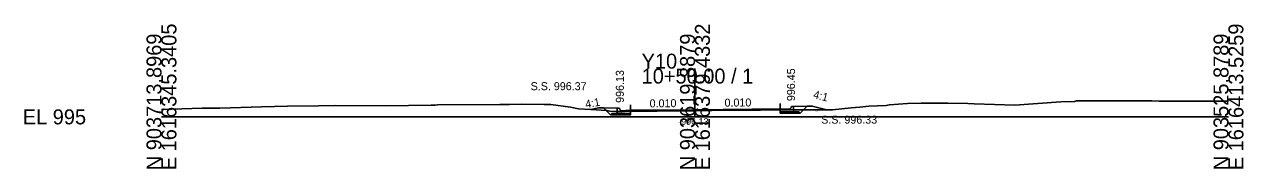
# Model space of a CAD drawing. Extents: x -26 to 203, y -10 to 3046.
# Drawn here: x -25.7 to 202.8, y 490.3 to 517.3 of the extents above; entities that cross this region are included whole.
import ezdxf

# ---------------------------------------------------------------- set-up
doc = ezdxf.new("R2010")
doc.units = 0
for name, color, linetype in [('Exist Cross Section Cell', 7, 'Continuous'), ('Exist XS Center Line Elevation Label', 7, 'Continuous'), ('Exist XS Ground Line', 7, 'Continuous'), ('Prop XS Dump Level', 7, 'Continuous'), ('Prop XS Earthwork Shape', 7, 'Continuous'), ('Prop XS EOT Tick Mark', 7, 'Continuous'), ('Prop XS Finish Grade CurbGutter', 7, 'Continuous'), ('Prop XS Finish Grade Earthwork', 7, 'Continuous'), ('Prop XS Finish Grade Pavement', 7, 'Continuous'), ('Prop XS Hydro Elevations', 7, 'Continuous'), ('Prop XS Pvmt Edge Slope', 7, 'Continuous'), ('Prop XS SE Text', 7, 'Continuous'), ('Prop XS Side Slope Text', 7, 'Continuous'), ('Prop XS SS Elevation Text', 7, 'Continuous'), ('Prop XS Subgrade CurbGutter', 7, 'Continuous'), ('Prop XS Subgrade Earthwork', 7, 'Continuous')]:
    doc.layers.add(name, color=color, linetype=linetype)

msp = doc.modelspace()

# ---------------------------------------------------------------- linework, layer by layer
at = {"layer": 'Exist Cross Section Cell'}
for p, q in [((100, 500), (100, 509.04)), ((0, 500), (100, 500)), ((100, 500), (200, 500))]:
    msp.add_line(p, q, dxfattribs=at)
at = {"layer": 'Exist XS Ground Line'}
for p, q in [((159.97, 502.21), (168.55, 502.81)), ((168.55, 502.81), (171.14, 502.88)), ((171.14, 502.88), (171.57, 503.01)), ((171.57, 503.01), (172.61, 503)), ((172.61, 503), (175.59, 502.98)), ((175.59, 502.98), (184.21, 503)), ((184.21, 503), (185.63, 502.99)), ((185.63, 502.99), (186.98, 502.96)), ((186.98, 502.96), (195.33, 502.93)), ((195.33, 502.93), (197.66, 502.94)), ((197.66, 502.94), (200, 502.95)), ((0, 501.41), (7.66, 501.62)), ((7.66, 501.62), (10.95, 501.66)), ((10.95, 501.66), (18.76, 501.85)), ((18.76, 501.85), (23.63, 501.98)), ((23.63, 501.98), (29.42, 502.05)), ((29.42, 502.05), (32.71, 502.1)), ((32.71, 502.1), (42.06, 502.09)), ((42.06, 502.09), (50.58, 502.19)), ((50.58, 502.19), (51.28, 502.21)), ((51.28, 502.21), (51.72, 502.23)), ((51.72, 502.23), (63.41, 502.29)), ((63.41, 502.29), (65.25, 502.34)), ((65.25, 502.34), (67.55, 502.39)), ((67.55, 502.39), (71.76, 502.34)), ((71.76, 502.34), (73, 502.31)), ((73, 502.31), (76.67, 501.8)), ((76.67, 501.8), (78.2, 501.5)), ((78.2, 501.5), (80.49, 501.37)), ((80.49, 501.37), (83.42, 501.2)), ((83.42, 501.2), (84.07, 501.05)), ((84.07, 501.05), (85.23, 501.03)), ((85.23, 501.03), (86.1, 501.02)), ((86.1, 501.02), (87.82, 501.05)), ((87.82, 501.05), (92.9, 501.1)), ((92.9, 501.1), (94.69, 501.14)), ((94.69, 501.14), (100.24, 501.13)), ((100.24, 501.13), (106.07, 501.24)), ((106.07, 501.24), (109.24, 501.26)), ((109.24, 501.26), (112.27, 501.27)), ((112.27, 501.27), (116.88, 501.29)), ((116.88, 501.29), (122.28, 501.32)), ((122.28, 501.32), (122.64, 501.32)), ((122.64, 501.32), (125.04, 501.33)), ((125.04, 501.33), (125.75, 501.33)), ((125.75, 501.33), (129.3, 501.69)), ((129.3, 501.69), (130.91, 501.84)), ((130.91, 501.84), (132.59, 501.98)), ((132.59, 501.98), (135.86, 502.14)), ((135.86, 502.14), (136.46, 502.27)), ((136.46, 502.27), (139.85, 502.53)), ((139.85, 502.53), (142.37, 502.57)), ((142.37, 502.57), (147.48, 502.59)), ((147.48, 502.59), (151.15, 502.5)), ((151.15, 502.5), (152.31, 502.46)), ((152.31, 502.46), (159.97, 502.21))]:
    msp.add_line(p, q, dxfattribs=at)
at = {"layer": 'Prop XS Dump Level'}
for p, q in [((100, 501.35), (87.92, 501.23)), ((116, 501.51), (100, 501.35))]:
    msp.add_line(p, q, dxfattribs=at)
at = {"layer": 'Prop XS Earthwork Shape'}
for points in [[(80.56, 501.36), (83.33, 501.2), (82.85, 501.68), (81.92, 501.7)], [(83.33, 501.2), (83.42, 501.2), (84.07, 501.05), (85.23, 501.03), (85.42, 501.03), (85.42, 500.63), (84.42, 500.62), (84.17, 500.36)], [(87.92, 500.65), (85.42, 500.63), (84.42, 500.62), (84.17, 500.36), (87.92, 500.4)], [(85.42, 501.03), (86.1, 501.02), (87.82, 501.05), (87.92, 501.05), (87.92, 500.65), (85.42, 500.63)], [(116, 501.29), (116.88, 501.29), (118.5, 501.3), (118.5, 500.96), (116, 500.93)], [(119.5, 500.97), (119.75, 500.72), (116, 500.68), (116, 500.93), (118.5, 500.96)], [(118.5, 501.3), (120.34, 501.31), (119.75, 500.72), (119.5, 500.97), (118.5, 500.96)], [(120.34, 501.31), (121.02, 501.99), (122, 502.01), (124.69, 501.33), (122.64, 501.32), (122.28, 501.32)]]:
    msp.add_lwpolyline(points, close=True, dxfattribs=at)
at = {"layer": 'Prop XS EOT Tick Mark'}
for p, q in [((87.92, 501.23), (87.92, 502.23)), ((116, 501.51), (116, 502.51))]:
    msp.add_line(p, q, dxfattribs=at)
at = {"layer": 'Prop XS Finish Grade CurbGutter'}
for p, q in [((85.42, 501.63), (85.67, 501.63)), ((85.67, 501.63), (85.79, 501.6)), ((85.89, 501.51), (85.79, 501.6)), ((85.95, 501.26), (85.89, 501.51)), ((86.04, 501.17), (85.95, 501.26)), ((86.17, 501.14), (86.04, 501.17)), ((87.92, 501.23), (86.17, 501.14)), ((116, 501.51), (117.75, 501.46)), ((117.75, 501.46), (117.87, 501.48)), ((117.87, 501.48), (117.97, 501.57)), ((117.97, 501.57), (118.03, 501.82)), ((118.03, 501.82), (118.12, 501.92)), ((118.25, 501.95), (118.12, 501.92)), ((118.5, 501.95), (118.25, 501.95))]:
    msp.add_line(p, q, dxfattribs=at)
at = {"layer": 'Prop XS Finish Grade Earthwork'}
for p, q in [((80.56, 501.36), (81.92, 501.7)), ((85.42, 501.63), (81.92, 501.7)), ((118.5, 501.95), (122, 502.01)), ((122, 502.01), (124.69, 501.33))]:
    msp.add_line(p, q, dxfattribs=at)
at = {"layer": 'Prop XS Finish Grade Pavement'}
for p, q in [((87.92, 501.23), (100, 501.35)), ((100, 501.35), (116, 501.51))]:
    msp.add_line(p, q, dxfattribs=at)
at = {"layer": 'Prop XS Pvmt Edge Slope'}
for p, q in [((84.42, 500.62), (84.17, 500.36)), ((85.42, 500.63), (84.42, 500.62)), ((118.5, 500.96), (119.5, 500.97)), ((119.5, 500.97), (119.75, 500.72))]:
    msp.add_line(p, q, dxfattribs=at)
at = {"layer": 'Prop XS Subgrade CurbGutter'}
for p, q in [((85.42, 500.63), (85.42, 501.63)), ((87.92, 500.65), (85.42, 500.63)), ((87.92, 501.23), (87.92, 500.65)), ((116, 501.51), (116, 500.93)), ((116, 500.93), (118.5, 500.96)), ((118.5, 500.96), (118.5, 501.95))]:
    msp.add_line(p, q, dxfattribs=at)
at = {"layer": 'Prop XS Subgrade Earthwork'}
for p, q in [((84.17, 500.36), (82.85, 501.68)), ((87.92, 500.65), (87.92, 501.05)), ((87.92, 500.65), (87.92, 500.4)), ((116, 500.93), (116, 501.29)), ((116, 500.93), (116, 500.68)), ((116, 500.68), (119.75, 500.72)), ((119.75, 500.72), (121.04, 502.01)), ((87.92, 500.4), (84.17, 500.36))]:
    msp.add_line(p, q, dxfattribs=at)

# ---------------------------------------------------------------- texts
at = {"layer": 'Exist Cross Section Cell'}
for s, p in [('E 1616345.3405', (2.8, 490)), ('E 1616379.4332', (102.8, 490)), ('E 1616413.5259', (202.8, 490)), ('N 903713.8969', (0, 490)), ('N 903619.8879', (100, 490)), ('N 903525.8789', (200, 490))]:
    msp.add_text(s, height=2.8, rotation=90, dxfattribs=at).set_placement(p)
for s, p in [('Y10', (90, 509.04)), ('10+50.00 / 1', (90, 506.24)), ('EL 995', (-26, 498.6))]:
    msp.add_text(s, height=2.8, dxfattribs=at).set_placement(p)
at = {"layer": 'Exist XS Center Line Elevation Label'}
msp.add_text('996.13', height=1.25, dxfattribs=at).set_placement((97.42, 498.51))
at = {"layer": 'Prop XS Dump Level'}
for p in [(86.1, 500.72), (122.27, 501.02)]:
    msp.add_text('Eop', height=0.3, dxfattribs=at).set_placement(p)
at = {"layer": 'Prop XS Hydro Elevations'}
for s, p in [('996.13', (86.67, 502.63)), ('996.45', (118.75, 502.95))]:
    msp.add_text(s, height=1.5, rotation=90, dxfattribs=at).set_placement(p)
at = {"layer": 'Prop XS SE Text'}
for p in [(91.51, 501.77), (105.55, 501.91)]:
    msp.add_text('0.010', height=1.5, rotation=0.5729, dxfattribs=at).set_placement(p)
at = {"layer": 'Prop XS Side Slope Text'}
for rotation, p in [(10.5187, (79.57, 501.6)), (345.9638, (122.06, 503.54))]:
    msp.add_text('4:1', height=1.5, rotation=rotation, dxfattribs=at).set_placement(p)
at = {"layer": 'Prop XS SS Elevation Text'}
for s, p in [('S.S. 996.37', (69.2, 505)), ('S.S. 996.33', (123.66, 498.73))]:
    msp.add_text(s, height=1.5, dxfattribs=at).set_placement(p)

doc.saveas('drawing.dxf')
